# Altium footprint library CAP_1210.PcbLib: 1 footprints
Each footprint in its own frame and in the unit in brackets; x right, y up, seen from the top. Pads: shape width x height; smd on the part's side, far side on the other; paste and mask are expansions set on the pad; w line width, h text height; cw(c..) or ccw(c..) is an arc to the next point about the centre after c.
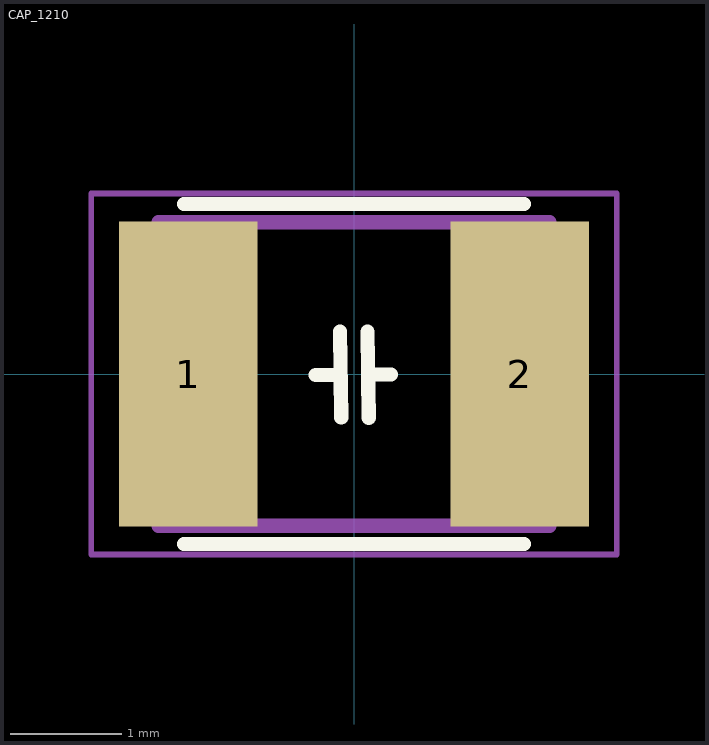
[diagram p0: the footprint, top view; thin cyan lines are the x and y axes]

## CAP_1210 [mm]
pads (2):
  rect 1.24x2.73 smd: 1(-1.485,0) 2(1.485,0)
Top Overlay:
  lines w0.127: -1.524,-1.524 1.524,-1.524 ; -1.524,1.524 1.524,1.524 ; -0.343,-0.008 -0.12,-0.008 ; -0.126,0.382 -0.115,-0.388 ; 0.121,0.378 0.132,-0.392 ; 0.153,-0.004 0.333,-0.004
Mechanical 13:
  lines w0.127: -1.75,-1.36 1.75,-1.36 1.75,1.36 -1.75,1.36 -1.75,-1.36
Mechanical 15:
  lines w0.05: -2.355,-1.617 2.355,-1.617 2.355,1.617 -2.355,1.617 -2.355,-1.617
3D body "CAP_1210.STEP": height 1.97, standoff -0.03, extent -1.526,-1.206 1.674,1.294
